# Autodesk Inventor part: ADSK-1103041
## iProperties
Shininess: 11.0
Length Units: 11269
Angle Units: 11279
Time Units: 11290
Mass Units: 11286
Length Display Precision: 2
Angle Display Precision: 2
Compacted: True
Created: 2000-07
Part Number: ADSK-1103041
Document SubType Name: Modeling
Material: Cast Steel
Description: ENGINE CASE - SIDE
Mass: 109.735 g
Surface Area: 158.987 cm^2
Volume: 13.979 cm^3
Density: 7.85 g/cm^3
Density: 0.0
Volumn: 0.0
Area: 0.0
PropertySet Name: Model Information
Control State: 0
Master: False
Checked Out: False
Author: Autodesk, Inc.
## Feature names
1. Fillet48
2. Fillet49
3. Fillet51
